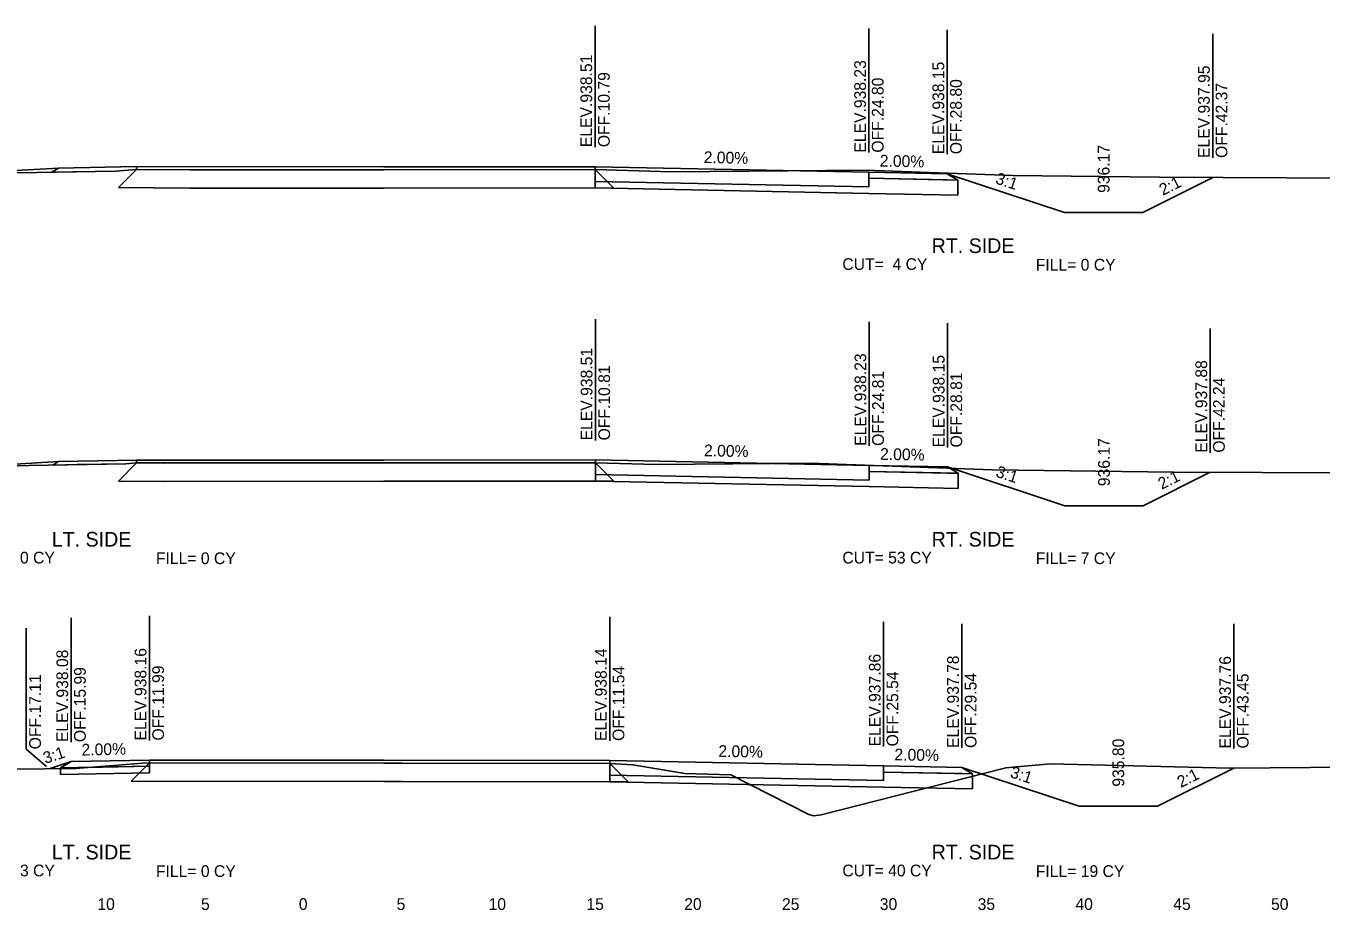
# Model space of a CAD drawing. Extents: x -4 to 359, y 0 to 1436.
# Drawn here: x 234.2 to 300.4, y 750.5 to 795.7 of the extents above; entities that cross this region are included whole.
import ezdxf

# ---------------------------------------------------------------- set-up
doc = ezdxf.new("R2010")
doc.units = 0
for name, color, linetype in [('XS-Existing subsurface-pavement', 7, 'Continuous'), ('XS-Existing surface-ground', 7, 'Continuous'), ('XS-Proposed Finish Grade', 7, 'Continuous'), ('XS-Proposed subsurface-aggregate layer 1', 7, 'Continuous'), ('XS-Proposed surface-ground', 7, 'Continuous'), ('XS-Proposed surface-pavement', 7, 'Continuous'), ('XS-Proposed surface-shoulder', 7, 'Continuous'), ('XS-Text-ditch slope', 7, 'Continuous'), ('XS-Text-earthwork labels', 7, 'Continuous'), ('XS-Text-offset label', 7, 'Continuous'), ('XS-Text-pavement elevation', 7, 'Continuous'), ('XS-Text-pavement slope', 7, 'Continuous'), ('XS-Text-profile report', 7, 'Continuous'), ('XS-Text-shoulder elevation', 7, 'Continuous'), ('XS-Text-shoulder slope', 7, 'Continuous'), ('XS-Text-tie elevation', 7, 'Continuous'), ('XS-Text-tie offset', 7, 'Continuous')]:
    doc.layers.add(name, color=color, linetype=linetype)

msp = doc.modelspace()

# ---------------------------------------------------------------- linework, layer by layer
at = {"layer": 'XS-Existing subsurface-pavement'}
for p, q in [((239.861, 788.344), (238.932, 787.415)), ((263.295, 788.339), (264.232, 787.403)), ((238.932, 787.415), (242.575, 787.384)), ((242.584, 787.384), (252.501, 787.393)), ((252.501, 787.393), (264.232, 787.403)), ((239.859, 773.336), (238.929, 772.406)), ((263.311, 773.343), (264.248, 772.406)), ((238.929, 772.406), (241.268, 772.387)), ((241.277, 772.387), (252.501, 772.396)), ((252.501, 772.396), (264.248, 772.406)), ((240.51, 757.994), (239.573, 757.057)), ((264.043, 757.974), (264.981, 757.035)), ((239.573, 757.057), (252.5, 757.051)), ((252.5, 757.051), (253.436, 757.05)), ((253.435, 757.05), (264.981, 757.035))]:
    msp.add_line(p, q, dxfattribs=at)
at = {"layer": 'XS-Existing surface-ground'}
for p, q in [((231.111, 788.127), (238.798, 788.253)), ((238.798, 788.253), (239.861, 788.344)), ((239.861, 788.344), (242.583, 788.322)), ((242.583, 788.322), (252.5, 788.33)), ((252.5, 788.33), (263.295, 788.339)), ((263.295, 788.339), (267.196, 788.22)), ((267.196, 788.22), (277.112, 788.306)), ((277.112, 788.306), (284.637, 788.032)), ((284.637, 788.032), (292.149, 787.945)), ((292.149, 787.945), (307.025, 787.875)), ((230.372, 773.093), (234.35, 773.207)), ((234.35, 773.207), (239.305, 773.288)), ((239.305, 773.288), (239.859, 773.336)), ((239.859, 773.336), (241.276, 773.324)), ((241.276, 773.324), (252.5, 773.334)), ((252.5, 773.334), (263.311, 773.343)), ((263.311, 773.343), (266.41, 773.248)), ((266.41, 773.248), (274.286, 773.316)), ((274.286, 773.316), (283.595, 772.978)), ((283.595, 772.978), (292.891, 772.87)), ((292.891, 772.87), (303.722, 772.819)), ((233.587, 757.672), (236.758, 757.705)), ((236.758, 757.705), (240.161, 757.987)), ((240.161, 757.987), (240.51, 757.994)), ((240.51, 757.994), (252.5, 757.988)), ((252.5, 757.988), (253.436, 757.988)), ((253.436, 757.988), (264.043, 757.974)), ((264.043, 757.974), (265.227, 757.899)), ((265.227, 757.899), (267.886, 757.463)), ((267.886, 757.463), (270.228, 757.388)), ((274.857, 755.341), (284.293, 757.745)), ((284.293, 757.745), (286.569, 757.954)), ((286.569, 757.954), (295.745, 757.733)), ((295.745, 757.733), (303.88, 757.797)), ((270.228, 757.388), (274.229, 755.352)), ((274.229, 755.352), (274.474, 755.291)), ((274.474, 755.291), (274.857, 755.341))]:
    msp.add_line(p, q, dxfattribs=at)
at = {"layer": 'XS-Proposed Finish Grade'}
for points in [[(239.861, 788.49), (252.5, 788.476), (263.295, 788.485)], [(263.295, 788.485), (277.295, 788.205)], [(277.295, 788.205), (281.295, 788.125)], [(239.859, 773.482), (252.5, 773.479), (263.311, 773.489)], [(263.311, 773.489), (277.311, 773.209)], [(277.311, 773.209), (281.311, 773.129)], [(240.51, 758.14), (236.51, 758.06)], [(240.51, 758.14), (252.5, 758.134), (264.043, 758.12)], [(264.043, 758.12), (278.045, 757.84)], [(278.045, 757.84), (282.045, 757.76)]]:
    msp.add_lwpolyline(points, dxfattribs=at)
at = {"layer": 'XS-Proposed subsurface-aggregate layer 1'}
for points in [[(263.295, 787.735), (277.295, 787.455)], [(263.295, 787.402), (263.295, 787.735)], [(281.834, 787.031), (277.295, 787.122), (263.295, 787.402)], [(277.295, 787.455), (277.295, 787.893)], [(277.295, 787.893), (281.834, 787.802)], [(281.834, 787.802), (281.834, 787.031)], [(263.311, 772.739), (277.311, 772.459)], [(263.311, 772.405), (263.311, 772.739)], [(277.311, 772.459), (277.311, 772.896)], [(277.311, 772.896), (281.85, 772.805)], [(281.85, 772.805), (281.85, 772.035)], [(281.85, 772.035), (277.311, 772.125), (263.311, 772.405)], [(240.51, 757.828), (235.972, 757.737)], [(235.972, 757.737), (235.972, 757.403)], [(235.972, 757.403), (240.51, 757.494)], [(240.51, 757.494), (240.51, 757.828)], [(278.045, 757.09), (278.045, 757.527)], [(278.045, 757.527), (282.583, 757.436)], [(264.043, 757.37), (278.045, 757.09)], [(264.043, 757.036), (264.043, 757.37)], [(282.583, 756.666), (278.045, 756.756), (264.043, 757.036)], [(282.583, 757.436), (282.583, 756.666)]]:
    msp.add_lwpolyline(points, dxfattribs=at)
at = {"layer": 'XS-Proposed surface-ground'}
for points in [[(235.861, 788.41), (230.861, 788.131)], [(281.295, 788.125), (287.295, 786.145), (291.295, 786.145), (294.87, 787.932)], [(235.859, 773.402), (230.859, 773.107)], [(281.311, 773.129), (287.311, 771.149), (291.311, 771.149), (294.737, 772.861)], [(236.51, 758.06), (235.392, 757.691)], [(282.045, 757.76), (288.045, 755.78), (292.045, 755.78), (295.954, 757.734)]]:
    msp.add_lwpolyline(points, dxfattribs=at)
at = {"layer": 'XS-Proposed surface-pavement'}
for points in [[(239.861, 788.49), (239.861, 788.344)], [(263.295, 788.485), (252.5, 788.476), (239.861, 788.49)], [(239.861, 788.344), (252.5, 788.33), (263.295, 788.339)], [(263.295, 788.485), (277.295, 788.205)], [(263.295, 787.735), (263.295, 788.485)], [(263.295, 788.339), (263.295, 788.485)], [(277.295, 788.205), (277.295, 787.455)], [(277.295, 787.455), (263.295, 787.735)], [(263.311, 773.489), (252.5, 773.479), (239.859, 773.482)], [(239.859, 773.482), (239.859, 773.336)], [(263.311, 773.489), (277.311, 773.209)], [(263.311, 772.739), (263.311, 773.489)], [(263.311, 773.343), (263.311, 773.489)], [(239.859, 773.336), (252.5, 773.334), (263.311, 773.343)], [(277.311, 772.459), (263.311, 772.739)], [(277.311, 773.209), (277.311, 772.459)], [(240.51, 758.14), (240.51, 757.994)], [(264.043, 758.12), (252.5, 758.134), (240.51, 758.14)], [(240.51, 757.994), (252.5, 757.988), (264.043, 757.974)], [(264.043, 758.12), (278.045, 757.84)], [(264.043, 757.37), (264.043, 758.12)], [(264.043, 757.974), (264.043, 758.12)], [(278.045, 757.84), (278.045, 757.09)], [(278.045, 757.09), (264.043, 757.37)]]:
    msp.add_lwpolyline(points, dxfattribs=at)
at = {"layer": 'XS-Proposed surface-shoulder'}
for p, q in [((235.861, 788.41), (235.51, 788.199)), ((238.798, 788.253), (235.51, 788.199)), ((239.861, 788.344), (238.798, 788.253)), ((235.859, 773.402), (235.568, 773.227)), ((236.827, 773.248), (235.568, 773.227)), ((239.305, 773.288), (236.827, 773.248)), ((236.827, 773.248), (236.827, 773.248)), ((239.859, 773.336), (239.305, 773.288))]:
    msp.add_line(p, q, dxfattribs=at)
for points in [[(239.861, 788.49), (235.861, 788.41)], [(277.295, 788.205), (281.295, 788.125), (281.834, 787.802)], [(277.295, 787.893), (277.295, 788.205)], [(281.834, 787.802), (281.295, 787.813), (277.295, 787.893)], [(239.859, 773.482), (235.859, 773.402)], [(277.311, 773.209), (281.311, 773.129), (281.85, 772.805)], [(277.311, 772.896), (277.311, 773.209)], [(281.85, 772.805), (281.311, 772.816), (277.311, 772.896)], [(240.51, 758.14), (236.51, 758.06), (235.972, 757.737)], [(240.51, 757.828), (240.51, 758.14)], [(235.972, 757.737), (236.51, 757.748), (240.51, 757.828)], [(278.045, 757.84), (282.045, 757.76), (282.583, 757.436)], [(278.045, 757.527), (278.045, 757.84)], [(282.583, 757.436), (282.045, 757.447), (278.045, 757.527)]]:
    msp.add_lwpolyline(points, dxfattribs=at)
at = {"layer": 'XS-Text-tie offset'}
for p, q in [((263.295, 789.485), (263.295, 795.685)), ((277.295, 789.205), (277.295, 795.555)), ((281.295, 789.125), (281.295, 795.477)), ((294.87, 788.932), (294.87, 795.284)), ((263.311, 774.489), (263.311, 780.689)), ((277.311, 774.209), (277.311, 780.559)), ((281.311, 774.129), (281.311, 780.481)), ((294.737, 773.861), (294.737, 780.211)), ((236.51, 759.06), (236.51, 765.41)), ((240.51, 759.14), (240.51, 765.518)), ((264.043, 759.12), (264.043, 765.47)), ((234.218, 758.691), (234.218, 764.891)), ((278.045, 758.84), (278.045, 765.218)), ((282.045, 758.76), (282.045, 765.11)), ((295.954, 758.734), (295.954, 765.112)), ((234.218, 758.691), (235.246, 757.816))]:
    msp.add_line(p, q, dxfattribs=at)

# ---------------------------------------------------------------- texts
at = {"layer": 'XS-Text-ditch slope'}
for s, rotation, p in [('3:1', 341.73711, (283.724, 787.639)), ('2:1', 26.56505, (292.322, 786.994)), ('3:1', 341.73711, (283.74, 772.643)), ('2:1', 26.56505, (292.263, 771.96)), ('3:1', 18.26289, (235.192, 757.941)), ('3:1', 341.73711, (284.474, 757.274)), ('2:1', 26.56505, (293.239, 756.712))]:
    msp.add_text(s, height=0.6, rotation=rotation, dxfattribs=at).set_placement(p)
at = {"layer": 'XS-Text-earthwork labels'}
for s, height, p in [('RT. SIDE', 0.75, (280.501, 784.069)), (' CUT=  4 CY           ', 0.6, (275.715, 783.204)), ('FILL= 0 CY           ', 0.6, (285.826, 783.172)), ('LT. SIDE', 0.75, (235.522, 769.059)), ('RT. SIDE', 0.75, (280.501, 769.059)), (' CUT= 0 CY           ', 0.6, (231.335, 768.194)), ('FILL= 0 CY           ', 0.6, (240.846, 768.162)), (' CUT= 53 CY           ', 0.6, (275.715, 768.194)), ('FILL= 7 CY           ', 0.6, (285.826, 768.162)), ('LT. SIDE', 0.75, (235.522, 753.06)), ('RT. SIDE', 0.75, (280.501, 753.06)), (' CUT= 3 CY           ', 0.6, (231.335, 752.194)), ('FILL= 0 CY           ', 0.6, (240.846, 752.163)), (' CUT= 40 CY           ', 0.6, (275.715, 752.194)), ('FILL= 19 CY           ', 0.6, (285.826, 752.163))]:
    msp.add_text(s, height=height, dxfattribs=at).set_placement(p)
at = {"layer": 'XS-Text-offset label'}
for s, p in [('           10           ', (235.4, 750.477)), ('           5           ', (240.7, 750.477)), ('           0           ', (245.7, 750.477)), ('           0           ', (245.7, 750.477)), ('           5           ', (250.7, 750.477)), ('           10           ', (255.4, 750.477)), ('           15           ', (260.4, 750.477)), ('           20           ', (265.4, 750.477)), ('           25           ', (270.4, 750.477)), ('           30           ', (275.4, 750.477)), ('           35           ', (280.4, 750.477)), ('           40           ', (285.4, 750.477)), ('           45           ', (290.4, 750.477)), ('           50           ', (295.4, 750.477))]:
    msp.add_text(s, height=0.6, dxfattribs=at).set_placement(p)
at = {"layer": 'XS-Text-pavement elevation'}
for s, p in [('ELEV.938.51', (263.145, 789.485)), ('ELEV.938.23', (277.145, 789.205)), ('OFF.10.79', (264.045, 789.485)), ('OFF.24.80', (278.045, 789.205)), ('ELEV.938.51', (263.161, 774.489)), ('ELEV.938.23', (277.161, 774.209)), ('OFF.10.81', (264.061, 774.489)), ('OFF.24.81', (278.061, 774.209)), ('ELEV.938.08', (236.36, 759.06)), ('ELEV.938.16', (240.36, 759.14)), ('ELEV.938.14', (263.893, 759.12)), ('ELEV.937.86', (277.895, 758.84)), ('OFF.15.99', (237.26, 759.06)), ('OFF.11.99', (241.26, 759.14)), ('OFF.11.54', (264.793, 759.12)), ('OFF.25.54', (278.795, 758.84))]:
    msp.add_text(s, height=0.6, rotation=90, dxfattribs=at).set_placement(p)
at = {"layer": 'XS-Text-pavement slope'}
for p in [(268.845, 788.674), (268.861, 773.678), (269.594, 758.309)]:
    msp.add_text('2.00%', height=0.6, rotation=358.85424, dxfattribs=at).set_placement(p)
at = {"layer": 'XS-Text-profile report'}
for s, p in [('Pvmt_Surf_Asph_T2_L', (239.846, 788.489)), ('Pvmt_Surf_Asph_T_L', (239.847, 788.344)), ('Pvmt_Surf_Asph_T1', (252.486, 788.475)), ('Pvmt_Surf_Asph_T', (252.487, 788.329)), ('Pvmt_Surf_Asph_T1_R', (263.279, 788.484)), ('Pvmt_Surf_Asph_T_R', (263.28, 788.339)), ('Pvmt_Surf_Conc_T1_R', (277.28, 788.204)), ('Shldr_Surf_Asph_T11', (281.28, 788.124)), ('Dtch_Bkslp_1_T', (294.858, 787.932)), ('Pvmt_Surf_Conc_B_R', (263.28, 787.734)), ('Agg_Layer_1_B2', (263.284, 787.401)), ('Shldr_Surf_Asph_B13', (277.28, 787.892)), ('Pvmt_Surf_Conc_B1_R', (277.28, 787.454)), ('Shldr_Surf_Asph_B11', (281.28, 787.812)), ('Shldr_Surf_Asph_B21', (281.819, 787.801)), ('Agg_Layer_1_B11', (277.283, 787.121)), ('Agg_Layer_1_B12', (281.822, 787.03)), ('Rt_Agg_Layer_1_B13', (284.775, 786.971)), ('Dtch_Frslp_1_B', (287.284, 786.144)), ('Dtch_Bkslp_1_B', (291.284, 786.144)), ('Pvmt_Surf_Asph_T2_L', (239.843, 773.481)), ('Pvmt_Surf_Asph_T1', (252.486, 773.479)), ('Pvmt_Surf_Asph_T1_R', (263.295, 773.488)), ('Pvmt_Surf_Asph_T_L', (239.844, 773.335)), ('Pvmt_Surf_Asph_T', (252.487, 773.333)), ('Pvmt_Surf_Asph_T_R', (263.296, 773.342)), ('Pvmt_Surf_Conc_B_R', (263.296, 772.738)), ('Pvmt_Surf_Conc_T1_R', (277.295, 773.208)), ('Shldr_Surf_Asph_B13', (277.296, 772.895)), ('Shldr_Surf_Asph_T11', (281.296, 773.128)), ('Shldr_Surf_Asph_B11', (281.296, 772.815)), ('Shldr_Surf_Asph_B21', (281.835, 772.805)), ('Dtch_Bkslp_1_T', (294.725, 772.861)), ('Agg_Layer_1_B2', (263.299, 772.405)), ('Pvmt_Surf_Conc_B1_R', (277.295, 772.458)), ('Agg_Layer_1_B11', (277.299, 772.125)), ('Agg_Layer_1_B12', (281.838, 772.034)), ('Rt_Agg_Layer_1_B13', (284.791, 771.975)), ('Dtch_Frslp_1_B', (287.3, 771.148)), ('Dtch_Bkslp_1_B', (291.3, 771.148)), ('Pvmt_Surf_Asph_T2_L', (240.495, 758.139)), ('Pvmt_Surf_Asph_T1', (252.486, 758.133)), ('Fill_Slope_2_B', (235.381, 757.69)), ('Shldr_Surf_Asph_B2', (235.957, 757.736)), ('Shldr_Surf_Asph_T1', (236.496, 758.059)), ('Shldr_Surf_Asph_B1', (236.496, 757.747)), ('Shldr_Surf_Asph_B12', (240.495, 757.827)), ('Pvmt_Surf_Asph_T_L', (240.496, 757.993)), ('Agg_Layer_1_B', (240.5, 757.493)), ('Pvmt_Surf_Asph_T', (252.487, 757.987)), ('Pvmt_Surf_Asph_T1_R', (264.027, 758.119)), ('Pvmt_Surf_Asph_T_R', (264.028, 757.973)), ('Pvmt_Surf_Conc_T1_R', (278.029, 757.839)), ('Shldr_Surf_Asph_B13', (278.029, 757.526)), ('Shldr_Surf_Asph_T11', (282.029, 757.759)), ('Dtch_Bkslp_1_T', (295.942, 757.733)), ('Agg_Layer_1_B1', (235.96, 757.403)), ('Pvmt_Surf_Conc_B_R', (264.028, 757.369)), ('Agg_Layer_1_B2', (264.031, 757.036)), ('Pvmt_Surf_Conc_B1_R', (278.029, 757.089)), ('Shldr_Surf_Asph_B11', (282.029, 757.446)), ('Shldr_Surf_Asph_B21', (282.568, 757.436)), ('Agg_Layer_1_B11', (278.033, 756.756)), ('Agg_Layer_1_B12', (282.571, 756.665)), ('Rt_Agg_Layer_1_B13', (285.525, 756.606)), ('Dtch_Frslp_1_B', (288.033, 755.779)), ('Dtch_Bkslp_1_B', (292.033, 755.779))]:
    msp.add_text(s, height=0.00167, dxfattribs=at).set_placement(p)
at = {"layer": 'XS-Text-shoulder elevation'}
for s, p in [('ELEV.938.15', (281.145, 789.125)), ('OFF.28.80', (282.045, 789.125)), ('ELEV.938.15', (281.161, 774.129)), ('OFF.28.81', (282.061, 774.129)), ('ELEV.937.78', (281.895, 758.76)), ('OFF.29.54', (282.795, 758.76))]:
    msp.add_text(s, height=0.6, rotation=90, dxfattribs=at).set_placement(p)
at = {"layer": 'XS-Text-shoulder slope'}
for rotation, p in [(358.85424, (277.845, 788.494)), (358.85424, (277.861, 773.498)), (1.14576, (237.048, 758.371)), (358.85424, (278.595, 758.129))]:
    msp.add_text('2.00%', height=0.6, rotation=rotation, dxfattribs=at).set_placement(p)
at = {"layer": 'XS-Text-tie elevation'}
for s, p in [('ELEV.937.95', (294.72, 788.932)), ('OFF.42.37', (295.62, 788.932)), ('936.17', (289.595, 787.145)), ('ELEV.937.88', (294.587, 773.861)), ('OFF.42.24', (295.487, 773.861)), ('936.17', (289.611, 772.149)), ('ELEV.937.76', (295.804, 758.734)), ('OFF.17.11', (234.968, 758.691)), ('OFF.43.45', (296.704, 758.734)), ('935.80', (290.345, 756.78))]:
    msp.add_text(s, height=0.6, rotation=90, dxfattribs=at).set_placement(p)

doc.saveas('drawing.dxf')
